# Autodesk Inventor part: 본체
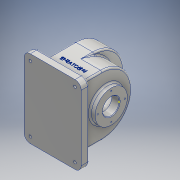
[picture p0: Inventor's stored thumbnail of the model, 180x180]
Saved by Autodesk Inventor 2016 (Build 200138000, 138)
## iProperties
Created: 2017-11
Part Number: 본체
Material: 알루미늄 6061
Document SubType Name: Modeling
Designer: 605-03
Mass: 2182.82 g
Surface Area: 1149.28 cm^2
Volume: 808.452 cm^3
Density: 2.7 g/cm^3
Appearance: 알루미늄 - 평지
Author: 605-03
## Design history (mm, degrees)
sketch "스케치1"
  geometry: L1 (0, 0)-(-80, 0); L2 (-80, 0)-(-80, -72); L3 (-80, 0)-(-80, 72); L4 (0, -58)-(-80, -58); L5 (0, 58)-(-80, 58); A1 r 58 centre (0, 0) between (0, -58) and (0, 58); 1 further point
  constraints: 10 end point, 2 perpendicular, 2 point on circle, 2 point on line, 2 vertical, 1 centre point, 1 coincident, 1 collinear, 1 horizontal
  dimensions: "d0" = 116 diameter of A1; "d2" = 80 distance of L1.start L1.end; "d5" = 72 distance of L1.end L2.end; "d6" = 80 distance of L4.start L4.end; "d7" = 80 distance of L5.start L5.end
extrude "돌출1" new body sketch "스케치1" distance "d8" = 38; taper "d9" = 0 deg
sketch "스케치2"
  geometry: L1 (0, 0)-(0, -23); L2 (-58, -80)-(58, -80) reference; L3 (58, -80)-(58, 0) reference; L4 (-58, 0)-(-58, -80) reference; L5 (58, -80)-(58, 0) reference; L6 (-58, -80)-(58, -80) reference; L7 (58, -23)-(58, -80); L8 (58, -80)-(-58, -80); L9 (-58, -80)-(-58, -23); L10 (-58, 0)-(-58, -80) reference; A1 r 58 centre (0, -23) between (58, -23) and (-58, -23); A2 r 58 centre (0, 0) between (58, 0) and (-58, 0) reference
  constraints: 8 end point, 2 point on circle, 2 point on line, 2 vertical, 1 centre point, 1 coincident, 1 collinear
  dimensions: "d10" = 23 distance of L1.start L1.end; "d11" = 116 diameter of A1
extrude "돌출2" join sketch "스케치2" distance "d12" = 38; taper "d13" = 0 deg
sketch "스케치3"
  geometry: L1 (-5, 133)-(81, 133); L2 (93, 121)-(93, -5); L3 (81, -17)-(-5, -17); L4 (-17, -5)-(-17, 121); L5 (38, 0)-(38, 116) reference; L6 (-17, 133)-(93, -17); L7 (93, 133)-(-17, -17); A1 r 12 centre (-5, 121) between (-5, 133) and (-17, 121); A2 r 12 centre (81, 121) between (93, 121) and (81, 133); A3 r 12 centre (81, -5) between (81, -17) and (93, -5); A4 r 12 centre (-5, -5) between (-17, -5) and (-5, -17); 2 further points
  constraints: 12 end point, 8 point on circle, 8 point on line, 8 tangent, 4 centre point, 3 midpoint, 2 parallel, 1 horizontal, 1 perpendicular
  dimensions: "d14" = 110 distance of L6.end L7.end; "d15" = 150 distance of L7.start L6.end; "d16" = 12 radius of A1; "d17" = 12 radius of A2; "d18" = 12 radius of A3; "d19" = 12 radius of A4
extrude "돌출3" join sketch "스케치3" distance "d20" = 15; taper "d21" = 0 deg
sketch "스케치4"
  geometry: L1 (-58, -23)-(-58, -65) reference; L2 (-58, -23)-(58, -23); C1 r 31 at (0, -15); C2 r 16 at (0, -15); 1 further point
  constraints: 2 centre point, 2 end point, 1 coincident, 1 horizontal, 1 vertical alignment
  dimensions: "d22" = 62 diameter of C1; "d24" = 8 distance from line of L2 C1.centre; "d25" = 32 diameter of C2
extrude "돌출4" join sketch "스케치4" distance "d26" = 10; taper "d27" = 0 deg
sketch "스케치5"
  geometry: 1 further point
sketch "스케치6" dims "d29" = 52
  geometry: L1 (-73.909, -50)-(73.909, -50) reference; L2 (73.909, -50)-(73.909, -65) reference; L3 (73.909, -65)-(-73.909, -65) reference; L4 (-73.909, -65)-(-73.909, -50) reference; C1 r 16 at (0, 0) reference; C2 r 31 at (0, 0) reference; 6 further points
  constraints: 2 vertical alignment, 1 coincident, 7 other
  dimensions: "d32" = 360 deg dimension on C2.centre point (0, 26) (derived)
hole "구멍1" sketch "스케치6" at (0, 26), (26, 0), (0, -26), (-26, 0) diameter "d34" = 2.459; stored, may be unused: countersink angle "d38" = 90 deg, drill point angle "d40" = 118 deg; dims "d35" = 6, "d36" = 4, "d37" = 2, "d39" = 8
sketch "스케치7"
  geometry: L1 (-75, -65)-(-58, -65) reference; L2 (-58, -65)-(58, -65) reference; L3 (58, -65)-(75, -65) reference; L4 (75, -65)-(75, -80) reference; L5 (75, -80)-(-75, -80) reference; L6 (-75, -80)-(-75, -65) reference; L7 (-58, -65)-(-58, 0) reference; L8 (58, 0)-(58, -65) reference; C1 r 37.5 at (0, -15); C2 r 16 at (0, -15); A1 r 58 centre (0, 0) between (58, 0) and (-58, 0) reference; 1 further point
  constraints: 2 centre point, 1 coincident, 1 vertical alignment
  dimensions: "d41" = 75 diameter of C1; "d42" = 15 distance of point (0, 0) C1.centre; "d43" = 32 diameter of C2
extrude "돌출5" join sketch "스케치7" distance "d44" = 9; taper "d45" = 0 deg
sketch "스케치8" dims "d47" = 58
  geometry: L1 (-74.314, -50)-(74.314, -50) reference; L2 (74.314, -50)-(74.314, -65) reference; L3 (74.314, -65)-(-74.314, -65) reference; L4 (-74.314, -65)-(-74.314, -50) reference; C1 r 16 at (0, 0) reference; C2 r 37.5 at (0, 0) reference; 9 further points
  constraints: 3 coincident, 3 vertical alignment, 2 horizontal alignment, 19 other
  dimensions: "d50" = 360 deg dimension on point (0, 0) point (0, 29) (derived)
hole "구멍2" sketch "스케치8" at (0, 29), (29, 0), (0, -29), (-29, 0) diameter "d52" = 2.459; stored, may be unused: countersink angle "d56" = 90 deg, drill point angle "d58" = 118 deg; dims "d53" = 6, "d54" = 4, "d55" = 2, "d57" = 8
node "작업 평면4"
sketch "스케치9"
  geometry: L1 (0, -58)-(0, 58) reference; L2 (0, 58)-(-38, 58) reference; L3 (-38, -58)-(-38, 58) reference; L4 (0, -58)-(-38, -58) reference; C1 r 6 at (-19, 0); 1 further point
  constraints: 1 centre point, 1 horizontal alignment, 1 midpoint
  dimensions: "d64" = 12 diameter of C1; "d65" = 19 distance from line of L1 C1.centre
extrude "돌출6" join sketch "스케치9" stored distance "d66" = 9; taper "d67" = 0 deg
hole "구멍3" diameter "d70" = 4.134; stored, may be unused: countersink angle "d74" = 90 deg, drill point angle "d76" = 118 deg; dims "d68" = 10, "d69" = 10, "d71" = 20, "d72" = 4, "d73" = 2, "d75" = 20
sketch "스케치10"
  geometry: L1 (0, 1)-(0, -31) reference; L2 (0, 0)-(38, 0) reference; L3 (0, 0)-(0, -15); L4 (0, -15)-(76, -15); L5 (76, -31)-(76, 1) reference; L6 (5, 0)-(5, 50); L7 (8, 53)-(30, 53); L8 (36, 30)-(68, 30); L9 (0, 0)-(0, 58) reference; L10 (76, 16)-(86, 16) reference; L11 (86, 16)-(86, 12.23) reference; L12 (86, 12.23)-(78, 12.23) reference; L13 (78, 12.23)-(77.261, 11) reference; L14 (77.261, 11)-(78, 9.771) reference; L15 (78, 9.771)-(86, 9.771) reference; L16 (86, 9.771)-(86, 1) reference; L17 (86, 1)-(76, 1) reference; L18 (76, 1)-(76, -31) reference; L19 (76, -31)-(86, -31) reference; L20 (86, -31)-(86, -39.77) reference; L21 (86, -39.77)-(78, -39.77) reference; L22 (78, -39.77)-(77.261, -41) reference; L23 (77.261, -41)-(78, -42.23) reference; L24 (78, -42.23)-(86, -42.23) reference; L25 (86, -42.23)-(86, -46) reference; L26 (86, -46)-(76, -46) reference; L27 (76, -46)-(76, -65) reference; L28 (76, -65)-(93, -65) reference; L29 (93, -65)-(93, -80) reference; L30 (93, -80)-(-17, -80) reference; L31 (-17, -80)-(-17, -65) reference; L32 (-17, -65)-(0, -65) reference; L33 (0, -65)-(0, -52.5) reference; L34 (0, -52.5)-(-9, -52.5) reference; L35 (-9, -52.5)-(-9, -45.23) reference; L36 (-9, -45.23)-(-1, -45.23) reference; L37 (-1, -45.23)-(-0.261, -44) reference; L38 (-0.261, -44)-(-1, -42.77) reference; L39 (-1, -42.77)-(-9, -42.77) reference; L40 (-9, -42.77)-(-9, -31) reference; L41 (-9, -31)-(0, -31) reference; L42 (0, -31)-(0, 1) reference; L43 (0, 1)-(-9, 1) reference; L44 (-9, 1)-(-9, 12.771) reference; L45 (-9, 12.771)-(-1, 12.771) reference; L46 (-1, 12.771)-(-0.261, 14) reference; L47 (-0.261, 14)-(-1, 15.23) reference; L48 (-1, 15.23)-(-9, 15.23) reference; L49 (-9, 15.23)-(-9, 22.5) reference; L50 (-9, 22.5)-(0, 22.5) reference; L51 (0, 22.5)-(0, 58) reference; L52 (0, 58)-(13, 58) reference; L53 (13, 58)-(13, 64) reference; L54 (13, 64)-(16.933, 64) reference; L55 (16.933, 64)-(16.933, 44) reference; L56 (16.933, 44)-(19, 42.758) reference; L57 (19, 42.758)-(21.067, 44) reference; L58 (21.067, 44)-(21.067, 64) reference; L59 (21.067, 64)-(25, 64) reference; L60 (25, 64)-(25, 58) reference; L61 (25, 58)-(38, 58) reference; L62 (38, 58)-(38, 35) reference; L63 (38, 35)-(76, 35) reference; L64 (76, 35)-(76, 16) reference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; A1 r 3 centre (8, 50) between (8, 53) and (5, 50); A2 r 3 centre (30, 50) between (33, 50) and (30, 53); A3 r 3 centre (36, 33) between (33, 33) and (36, 30); A4 r 3 centre (68, 27) between (71, 27) and (68, 30)
  constraints: 16 end point, 8 point on circle, 8 tangent, 4 centre point, 3 equal radius, 3 vertical, 2 midpoint, 2 point on line, 1 horizontal, 1 perpendicular
  dimensions: "d78" = 15 distance of L2.start L3.end; "d79" = 5 distance between parallel lines of L9 L6; "d82" = 5 distance between parallel lines of L52 L7; "d83" = 5 distance between parallel lines of L8 L63; "d85" = 5 distance between parallel lines of L62 L65; "d86" = 5 distance between parallel lines of L7 L61 (derived); "d88" = 5 distance between parallel lines of L64 L66; "d89" = 3 radius of A1
revolve "회전1" sketch "스케치10" stored, may be unused: angle "d90" = 90 deg
extrude "돌출7" cut sketch "스케치4" distance "d91" = 158.25; taper "d92" = 0 deg
fillet "모깎기1" dims "d93" = 3
chamfer "모따기1" distance "d94" = 1; stored, may be unused: second distance "d95" = 2, angle "d96" = 45 deg
hole "구멍4" diameter "d99" = 5; stored, may be unused: countersink angle "d103" = 90 deg, drill point angle "d105" = 0 deg; dims "d97" = 10, "d98" = 10, "d100" = 20, "d101" = 4, "d102" = 2, "d104" = 12
hole "구멍5" diameter "d108" = 5; stored, may be unused: countersink angle "d112" = 90 deg, drill point angle "d114" = 0 deg; dims "d106" = 10, "d107" = 10, "d109" = 20, "d110" = 4, "d111" = 2, "d113" = 12
hole "구멍6" diameter "d117" = 5; stored, may be unused: countersink angle "d121" = 90 deg, drill point angle "d123" = 0 deg; dims "d115" = 10, "d116" = 10, "d118" = 20, "d119" = 4, "d120" = 2, "d122" = 12
hole "구멍7" diameter "d126" = 5; stored, may be unused: countersink angle "d130" = 90 deg, drill point angle "d132" = 0 deg; dims "d124" = 10, "d125" = 10, "d127" = 20, "d128" = 4, "d129" = 2, "d131" = 12
hole "구멍8" diameter "d135" = 12; stored, may be unused: countersink angle "d139" = 90 deg, drill point angle "d141" = 0 deg; dims "d133" = 10, "d134" = 10, "d136" = 20, "d137" = 4, "d138" = 2, "d140" = 5
hole "구멍9" diameter "d144" = 12; stored, may be unused: countersink angle "d148" = 90 deg, drill point angle "d150" = 0 deg; dims "d142" = 10, "d143" = 10, "d145" = 20, "d146" = 4, "d147" = 2, "d149" = 5
hole "구멍10" diameter "d153" = 12; stored, may be unused: countersink angle "d157" = 90 deg, drill point angle "d159" = 0 deg; dims "d151" = 10, "d152" = 10, "d154" = 20, "d155" = 4, "d156" = 2, "d158" = 5
hole "구멍11" diameter "d162" = 12; stored, may be unused: countersink angle "d166" = 90 deg, drill point angle "d168" = 0 deg; dims "d160" = 10, "d161" = 10, "d163" = 20, "d164" = 4, "d165" = 2, "d167" = 5
sketch "스케치11"
  geometry: L1 (-3, 62)-(-3, 0) reference; L2 (78, -18)-(-8, -18) reference; 1 further point
  constraints: 1 other
  dimensions: "d169" = 38 distance from line of point (35, 22) L1; "d170" = 40 distance from line of L2 point (35, 22)
feature "엠보싱1" sketch "스케치11" dims "d0" = 116, "d2" = 80, "d5" = 72, "d6" = 80, "d7" = 80, "d10" = 23, "d11" = 116, "d171" = 0.5, "d172" = 0
chamfer "모따기2" distance "d173" = 1; stored, may be unused: second distance "d174" = 2, angle "d175" = 45 deg
node "솔리드1"
node "투영된 루프1"
node "투영된 루프2"
node "절단 모서리 투영1"
node "절단 모서리 투영2"
node "절단 모서리 투영3"
node "절단 모서리 투영4"
